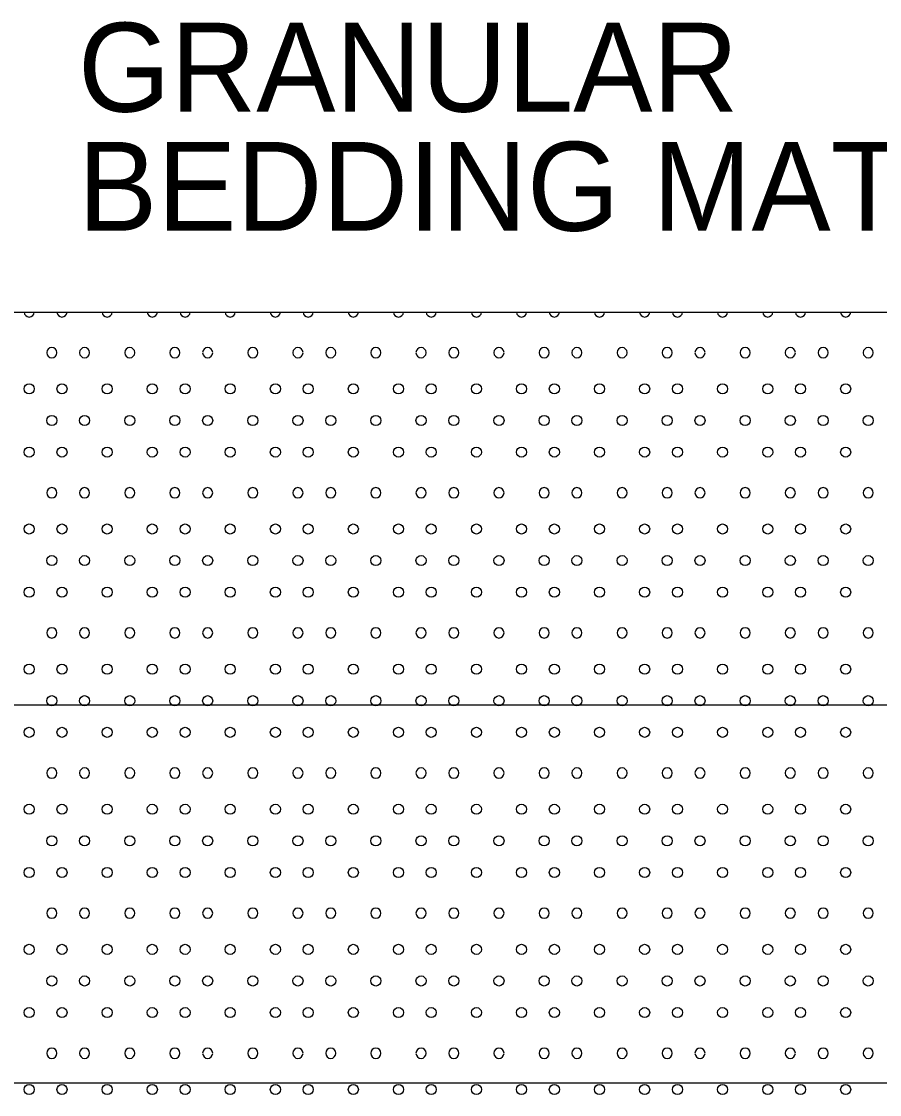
# Model space of a CAD drawing. Extents: x 49991.4 to 50021, y 49987.6 to 50011.4.
# Drawn here: x 50019.363 to 50019.942, y 50006.557 to 50007.281 of the extents above; entities that cross this region are included whole.
import ezdxf

# ---------------------------------------------------------------- set-up
doc = ezdxf.new("R2010")
doc.units = 0
doc.layers.add('Level 1', color=7, linetype='Continuous')
doc.layers.add('Level 2', color=7, linetype='Continuous')

msp = doc.modelspace()

# ---------------------------------------------------------------- linework, layer by layer
at = {"layer": 'Level 1'}
for p, q in [((50017.1193, 50007.085), (50020.46747, 50007.085)), ((50017.0193, 50006.81976), (50020.46747, 50006.81976)), ((50020.46747, 50006.56447), (50017.12756, 50006.5644))]:
    msp.add_line(p, q, dxfattribs=at)
for centre in [(50019.36773, 50007.03318), (50019.38987, 50007.03318), (50019.42035, 50007.03318), (50019.45083, 50007.03318), (50019.47297, 50007.03318), (50019.50345, 50007.03318), (50019.53393, 50007.03318), (50019.55607, 50007.03318), (50019.58655, 50007.03318), (50019.61703, 50007.03318), (50019.63917, 50007.03318), (50019.66965, 50007.03318), (50019.70013, 50007.03318), (50019.72227, 50007.03318), (50019.75275, 50007.03318), (50019.78323, 50007.03318), (50019.80537, 50007.03318), (50019.83585, 50007.03318), (50019.86633, 50007.03318), (50019.88847, 50007.03318), (50019.91895, 50007.03318), (50019.38297, 50007.01185), (50019.40511, 50007.01185), (50019.43559, 50007.01185), (50019.43559, 50007.01185), (50019.46607, 50007.01185), (50019.48821, 50007.01185), (50019.51869, 50007.01185), (50019.51869, 50007.01185), (50019.54917, 50007.01185), (50019.57131, 50007.01185), (50019.60179, 50007.01185), (50019.60179, 50007.01185), (50019.63227, 50007.01185), (50019.65441, 50007.01185), (50019.68489, 50007.01185), (50019.68489, 50007.01185), (50019.71537, 50007.01185), (50019.73751, 50007.01185), (50019.76799, 50007.01185), (50019.76799, 50007.01185), (50019.79847, 50007.01185), (50019.82061, 50007.01185), (50019.85109, 50007.01185), (50019.85109, 50007.01185), (50019.88157, 50007.01185), (50019.90371, 50007.01185), (50019.93419, 50007.01185), (50019.93419, 50007.01185), (50019.36773, 50006.99051), (50019.38987, 50006.99051), (50019.42035, 50006.99051), (50019.45083, 50006.99051), (50019.47297, 50006.99051), (50019.50345, 50006.99051), (50019.53393, 50006.99051), (50019.55607, 50006.99051), (50019.58655, 50006.99051), (50019.61703, 50006.99051), (50019.63917, 50006.99051), (50019.66965, 50006.99051), (50019.70013, 50006.99051), (50019.72227, 50006.99051), (50019.75275, 50006.99051), (50019.78323, 50006.99051), (50019.80537, 50006.99051), (50019.83585, 50006.99051), (50019.86633, 50006.99051), (50019.88847, 50006.99051), (50019.91895, 50006.99051), (50019.36773, 50006.93858), (50019.38987, 50006.93858), (50019.42035, 50006.93858), (50019.45083, 50006.93858), (50019.47297, 50006.93858), (50019.50345, 50006.93858), (50019.53393, 50006.93858), (50019.55607, 50006.93858), (50019.58655, 50006.93858), (50019.61703, 50006.93858), (50019.63917, 50006.93858), (50019.66965, 50006.93858), (50019.70013, 50006.93858), (50019.72227, 50006.93858), (50019.75275, 50006.93858), (50019.78323, 50006.93858), (50019.80537, 50006.93858), (50019.83585, 50006.93858), (50019.86633, 50006.93858), (50019.88847, 50006.93858), (50019.91895, 50006.93858), (50019.38297, 50006.91725), (50019.40511, 50006.91725), (50019.43559, 50006.91725), (50019.43559, 50006.91725), (50019.46607, 50006.91725), (50019.48821, 50006.91725), (50019.51869, 50006.91725), (50019.51869, 50006.91725), (50019.54917, 50006.91725), (50019.57131, 50006.91725), (50019.60179, 50006.91725), (50019.60179, 50006.91725), (50019.63227, 50006.91725), (50019.65441, 50006.91725), (50019.68489, 50006.91725), (50019.68489, 50006.91725), (50019.71537, 50006.91725), (50019.73751, 50006.91725), (50019.76799, 50006.91725), (50019.76799, 50006.91725), (50019.79847, 50006.91725), (50019.82061, 50006.91725), (50019.85109, 50006.91725), (50019.85109, 50006.91725), (50019.88157, 50006.91725), (50019.90371, 50006.91725), (50019.93419, 50006.91725), (50019.93419, 50006.91725), (50019.36773, 50006.89591), (50019.38987, 50006.89591), (50019.42035, 50006.89591), (50019.45083, 50006.89591), (50019.47297, 50006.89591), (50019.50345, 50006.89591), (50019.53393, 50006.89591), (50019.55607, 50006.89591), (50019.58655, 50006.89591), (50019.61703, 50006.89591), (50019.63917, 50006.89591), (50019.66965, 50006.89591), (50019.70013, 50006.89591), (50019.72227, 50006.89591), (50019.75275, 50006.89591), (50019.78323, 50006.89591), (50019.80537, 50006.89591), (50019.83585, 50006.89591), (50019.86633, 50006.89591), (50019.88847, 50006.89591), (50019.91895, 50006.89591), (50019.36773, 50006.84398), (50019.38987, 50006.84398), (50019.42035, 50006.84398), (50019.45083, 50006.84398), (50019.47297, 50006.84398), (50019.50345, 50006.84398), (50019.53393, 50006.84398), (50019.55607, 50006.84398), (50019.58655, 50006.84398), (50019.61703, 50006.84398), (50019.63917, 50006.84398), (50019.66965, 50006.84398), (50019.70013, 50006.84398), (50019.72227, 50006.84398), (50019.75275, 50006.84398), (50019.78323, 50006.84398), (50019.80537, 50006.84398), (50019.83585, 50006.84398), (50019.86633, 50006.84398), (50019.88847, 50006.84398), (50019.91895, 50006.84398), (50019.38297, 50006.82265), (50019.40511, 50006.82265), (50019.43559, 50006.82265), (50019.43559, 50006.82265), (50019.46607, 50006.82265), (50019.48821, 50006.82265), (50019.51869, 50006.82265), (50019.51869, 50006.82265), (50019.54917, 50006.82265), (50019.57131, 50006.82265), (50019.60179, 50006.82265), (50019.60179, 50006.82265), (50019.63227, 50006.82265), (50019.65441, 50006.82265), (50019.68489, 50006.82265), (50019.68489, 50006.82265), (50019.71537, 50006.82265), (50019.73751, 50006.82265), (50019.76799, 50006.82265), (50019.76799, 50006.82265), (50019.79847, 50006.82265), (50019.82061, 50006.82265), (50019.85109, 50006.82265), (50019.85109, 50006.82265), (50019.88157, 50006.82265), (50019.90371, 50006.82265), (50019.93419, 50006.82265), (50019.93419, 50006.82265), (50019.36773, 50006.80131), (50019.38987, 50006.80131), (50019.42035, 50006.80131), (50019.45083, 50006.80131), (50019.47297, 50006.80131), (50019.50345, 50006.80131), (50019.53393, 50006.80131), (50019.55607, 50006.80131), (50019.58655, 50006.80131), (50019.61703, 50006.80131), (50019.63917, 50006.80131), (50019.66965, 50006.80131), (50019.70013, 50006.80131), (50019.72227, 50006.80131), (50019.75275, 50006.80131), (50019.78323, 50006.80131), (50019.80537, 50006.80131), (50019.83585, 50006.80131), (50019.86633, 50006.80131), (50019.88847, 50006.80131), (50019.91895, 50006.80131), (50019.36773, 50006.74938), (50019.38987, 50006.74938), (50019.42035, 50006.74938), (50019.45083, 50006.74938), (50019.47297, 50006.74938), (50019.50345, 50006.74938), (50019.53393, 50006.74938), (50019.55607, 50006.74938), (50019.58655, 50006.74938), (50019.61703, 50006.74938), (50019.63917, 50006.74938), (50019.66965, 50006.74938), (50019.70013, 50006.74938), (50019.72227, 50006.74938), (50019.75275, 50006.74938), (50019.78323, 50006.74938), (50019.80537, 50006.74938), (50019.83585, 50006.74938), (50019.86633, 50006.74938), (50019.88847, 50006.74938), (50019.91895, 50006.74938), (50019.38297, 50006.72805), (50019.40511, 50006.72805), (50019.43559, 50006.72805), (50019.43559, 50006.72805), (50019.46607, 50006.72805), (50019.48821, 50006.72805), (50019.51869, 50006.72805), (50019.51869, 50006.72805), (50019.54917, 50006.72805), (50019.57131, 50006.72805), (50019.60179, 50006.72805), (50019.60179, 50006.72805), (50019.63227, 50006.72805), (50019.65441, 50006.72805), (50019.68489, 50006.72805), (50019.68489, 50006.72805), (50019.71537, 50006.72805), (50019.73751, 50006.72805), (50019.76799, 50006.72805), (50019.76799, 50006.72805), (50019.79847, 50006.72805), (50019.82061, 50006.72805), (50019.85109, 50006.72805), (50019.85109, 50006.72805), (50019.88157, 50006.72805), (50019.90371, 50006.72805), (50019.93419, 50006.72805), (50019.93419, 50006.72805), (50019.36773, 50006.70671), (50019.38987, 50006.70671), (50019.42035, 50006.70671), (50019.45083, 50006.70671), (50019.47297, 50006.70671), (50019.50345, 50006.70671), (50019.53393, 50006.70671), (50019.55607, 50006.70671), (50019.58655, 50006.70671), (50019.61703, 50006.70671), (50019.63917, 50006.70671), (50019.66965, 50006.70671), (50019.70013, 50006.70671), (50019.72227, 50006.70671), (50019.75275, 50006.70671), (50019.78323, 50006.70671), (50019.80537, 50006.70671), (50019.83585, 50006.70671), (50019.86633, 50006.70671), (50019.88847, 50006.70671), (50019.91895, 50006.70671), (50019.36773, 50006.65478), (50019.38987, 50006.65478), (50019.42035, 50006.65478), (50019.45083, 50006.65478), (50019.47297, 50006.65478), (50019.50345, 50006.65478), (50019.53393, 50006.65478), (50019.55607, 50006.65478), (50019.58655, 50006.65478), (50019.61703, 50006.65478), (50019.63917, 50006.65478), (50019.66965, 50006.65478), (50019.70013, 50006.65478), (50019.72227, 50006.65478), (50019.75275, 50006.65478), (50019.78323, 50006.65478), (50019.80537, 50006.65478), (50019.83585, 50006.65478), (50019.86633, 50006.65478), (50019.88847, 50006.65478), (50019.91895, 50006.65478), (50019.38297, 50006.63345), (50019.40511, 50006.63345), (50019.43559, 50006.63345), (50019.43559, 50006.63345), (50019.46607, 50006.63345), (50019.48821, 50006.63345), (50019.51869, 50006.63345), (50019.51869, 50006.63345), (50019.54917, 50006.63345), (50019.57131, 50006.63345), (50019.60179, 50006.63345), (50019.60179, 50006.63345), (50019.63227, 50006.63345), (50019.65441, 50006.63345), (50019.68489, 50006.63345), (50019.68489, 50006.63345), (50019.71537, 50006.63345), (50019.73751, 50006.63345), (50019.76799, 50006.63345), (50019.76799, 50006.63345), (50019.79847, 50006.63345), (50019.82061, 50006.63345), (50019.85109, 50006.63345), (50019.85109, 50006.63345), (50019.88157, 50006.63345), (50019.90371, 50006.63345), (50019.93419, 50006.63345), (50019.93419, 50006.63345), (50019.36773, 50006.61211), (50019.38987, 50006.61211), (50019.42035, 50006.61211), (50019.45083, 50006.61211), (50019.47297, 50006.61211), (50019.50345, 50006.61211), (50019.53393, 50006.61211), (50019.55607, 50006.61211), (50019.58655, 50006.61211), (50019.61703, 50006.61211), (50019.63917, 50006.61211), (50019.66965, 50006.61211), (50019.70013, 50006.61211), (50019.72227, 50006.61211), (50019.75275, 50006.61211), (50019.78323, 50006.61211), (50019.80537, 50006.61211), (50019.83585, 50006.61211), (50019.86633, 50006.61211), (50019.88847, 50006.61211), (50019.91895, 50006.61211), (50019.36773, 50006.56018), (50019.38987, 50006.56018), (50019.42035, 50006.56018), (50019.45083, 50006.56018), (50019.47297, 50006.56018), (50019.50345, 50006.56018), (50019.53393, 50006.56018), (50019.55607, 50006.56018), (50019.58655, 50006.56018), (50019.61703, 50006.56018), (50019.63917, 50006.56018), (50019.66965, 50006.56018), (50019.70013, 50006.56018), (50019.72227, 50006.56018), (50019.75275, 50006.56018), (50019.78323, 50006.56018), (50019.80537, 50006.56018), (50019.83585, 50006.56018), (50019.86633, 50006.56018), (50019.88847, 50006.56018), (50019.91895, 50006.56018)]:
    msp.add_circle(centre, 0.00341, dxfattribs=at)
for centre, start, end in [((50019.36773, 50007.08511), 181.83358, 358.16642), ((50019.38987, 50007.08511), 181.83358, 358.16642), ((50019.42035, 50007.08511), 181.83358, 358.16642), ((50019.45083, 50007.08511), 181.83358, 358.16642), ((50019.47297, 50007.08511), 181.83358, 358.16642), ((50019.50345, 50007.08511), 181.83358, 358.16642), ((50019.53393, 50007.08511), 181.83358, 358.16642), ((50019.55607, 50007.08511), 181.83358, 358.16642), ((50019.58655, 50007.08511), 181.83358, 358.16642), ((50019.61703, 50007.08511), 181.83358, 358.16642), ((50019.63917, 50007.08511), 181.83358, 358.16642), ((50019.66965, 50007.08511), 181.83358, 358.16642), ((50019.70013, 50007.08511), 181.83358, 358.16642), ((50019.72227, 50007.08511), 181.83358, 358.16642), ((50019.75275, 50007.08511), 181.83358, 358.16642), ((50019.78323, 50007.08511), 181.83358, 358.16642), ((50019.80537, 50007.08511), 181.83358, 358.16642), ((50019.83585, 50007.08511), 181.83358, 358.16642), ((50019.86633, 50007.08511), 181.83358, 358.16642), ((50019.88847, 50007.08511), 181.83358, 358.16642), ((50019.91895, 50007.08511), 181.83358, 358.16642), ((50019.38297, 50007.05768), 0, 180), ((50019.38297, 50007.05757), 180, 0), ((50019.40511, 50007.05768), 0, 180), ((50019.40511, 50007.05757), 180, 0), ((50019.43559, 50007.05768), 0, 180), ((50019.43559, 50007.05757), 180, 0), ((50019.43559, 50007.05757), 180, 0), ((50019.46607, 50007.05768), 0, 180), ((50019.46607, 50007.05757), 180, 0), ((50019.48821, 50007.05768), 0, 180), ((50019.48821, 50007.05757), 180, 0), ((50019.51869, 50007.05768), 0, 180), ((50019.51869, 50007.05757), 180, 0), ((50019.51869, 50007.05757), 180, 0), ((50019.54917, 50007.05768), 0, 180), ((50019.54917, 50007.05757), 180, 0), ((50019.57131, 50007.05768), 0, 180), ((50019.57131, 50007.05757), 180, 0), ((50019.60179, 50007.05768), 0, 180), ((50019.60179, 50007.05757), 180, 0), ((50019.60179, 50007.05757), 180, 0), ((50019.63227, 50007.05768), 0, 180), ((50019.63227, 50007.05757), 180, 0), ((50019.65441, 50007.05768), 0, 180), ((50019.65441, 50007.05757), 180, 0), ((50019.68489, 50007.05768), 0, 180), ((50019.68489, 50007.05757), 180, 0), ((50019.68489, 50007.05757), 180, 0), ((50019.71537, 50007.05768), 0, 180), ((50019.71537, 50007.05757), 180, 0), ((50019.73751, 50007.05768), 0, 180), ((50019.73751, 50007.05757), 180, 0), ((50019.76799, 50007.05768), 0, 180), ((50019.76799, 50007.05757), 180, 0), ((50019.76799, 50007.05757), 180, 0), ((50019.79847, 50007.05768), 0, 180), ((50019.79847, 50007.05757), 180, 0), ((50019.82061, 50007.05768), 0, 180), ((50019.82061, 50007.05757), 180, 0), ((50019.85109, 50007.05768), 0, 180), ((50019.85109, 50007.05757), 180, 0), ((50019.85109, 50007.05757), 180, 0), ((50019.88157, 50007.05768), 0, 180), ((50019.88157, 50007.05757), 180, 0), ((50019.90371, 50007.05768), 0, 180), ((50019.90371, 50007.05757), 180, 0), ((50019.93419, 50007.05768), 0, 180), ((50019.93419, 50007.05757), 180, 0), ((50019.93419, 50007.05757), 180, 0), ((50019.38297, 50006.96308), 0, 180), ((50019.38297, 50006.96297), 180, 0), ((50019.40511, 50006.96308), 0, 180), ((50019.40511, 50006.96297), 180, 0), ((50019.43559, 50006.96308), 0, 180), ((50019.43559, 50006.96297), 180, 0), ((50019.43559, 50006.96297), 180, 0), ((50019.46607, 50006.96308), 0, 180), ((50019.46607, 50006.96297), 180, 0), ((50019.48821, 50006.96308), 0, 180), ((50019.48821, 50006.96297), 180, 0), ((50019.51869, 50006.96308), 0, 180), ((50019.51869, 50006.96297), 180, 0), ((50019.51869, 50006.96297), 180, 0), ((50019.54917, 50006.96308), 0, 180), ((50019.54917, 50006.96297), 180, 0), ((50019.57131, 50006.96308), 0, 180), ((50019.57131, 50006.96297), 180, 0), ((50019.60179, 50006.96308), 0, 180), ((50019.60179, 50006.96297), 180, 0), ((50019.60179, 50006.96297), 180, 0), ((50019.63227, 50006.96308), 0, 180), ((50019.63227, 50006.96297), 180, 0), ((50019.65441, 50006.96308), 0, 180), ((50019.65441, 50006.96297), 180, 0), ((50019.68489, 50006.96308), 0, 180), ((50019.68489, 50006.96297), 180, 0), ((50019.71537, 50006.96308), 0, 180), ((50019.71537, 50006.96297), 180, 0), ((50019.73751, 50006.96308), 0, 180), ((50019.73751, 50006.96297), 180, 0), ((50019.76799, 50006.96308), 0, 180), ((50019.76799, 50006.96297), 180, 0), ((50019.76799, 50006.96297), 180, 0), ((50019.79847, 50006.96308), 0, 180), ((50019.79847, 50006.96297), 180, 0), ((50019.82061, 50006.96308), 0, 180), ((50019.82061, 50006.96297), 180, 0), ((50019.85109, 50006.96308), 0, 180), ((50019.85109, 50006.96297), 180, 0), ((50019.85109, 50006.96297), 180, 0), ((50019.88157, 50006.96308), 0, 180), ((50019.88157, 50006.96297), 180, 0), ((50019.90371, 50006.96308), 0, 180), ((50019.90371, 50006.96297), 180, 0), ((50019.93419, 50006.96308), 0, 180), ((50019.93419, 50006.96297), 180, 0), ((50019.93419, 50006.96297), 180, 0), ((50019.38297, 50006.86848), 0, 180), ((50019.38297, 50006.86837), 180, 0), ((50019.40511, 50006.86848), 0, 180), ((50019.40511, 50006.86837), 180, 0), ((50019.43559, 50006.86848), 0, 180), ((50019.43559, 50006.86837), 180, 0), ((50019.43559, 50006.86837), 180, 0), ((50019.46607, 50006.86848), 0, 180), ((50019.46607, 50006.86837), 180, 0), ((50019.48821, 50006.86848), 0, 180), ((50019.48821, 50006.86837), 180, 0), ((50019.51869, 50006.86848), 0, 180), ((50019.51869, 50006.86837), 180, 0), ((50019.51869, 50006.86837), 180, 0), ((50019.54917, 50006.86848), 0, 180), ((50019.54917, 50006.86837), 180, 0), ((50019.57131, 50006.86848), 0, 180), ((50019.57131, 50006.86837), 180, 0), ((50019.60179, 50006.86848), 0, 180), ((50019.60179, 50006.86837), 180, 0), ((50019.60179, 50006.86837), 180, 0), ((50019.63227, 50006.86848), 0, 180), ((50019.63227, 50006.86837), 180, 0), ((50019.65441, 50006.86848), 0, 180), ((50019.65441, 50006.86837), 180, 0), ((50019.68489, 50006.86848), 0, 180), ((50019.68489, 50006.86837), 180, 0), ((50019.68489, 50006.86837), 180, 0), ((50019.71537, 50006.86848), 0, 180), ((50019.71537, 50006.86837), 180, 0), ((50019.73751, 50006.86848), 0, 180), ((50019.73751, 50006.86837), 180, 0), ((50019.76799, 50006.86848), 0, 180), ((50019.76799, 50006.86837), 180, 0), ((50019.76799, 50006.86837), 180, 0), ((50019.79847, 50006.86848), 0, 180), ((50019.79847, 50006.86837), 180, 0), ((50019.82061, 50006.86848), 0, 180), ((50019.82061, 50006.86837), 180, 0), ((50019.85109, 50006.86848), 0, 180), ((50019.85109, 50006.86837), 180, 0), ((50019.85109, 50006.86837), 180, 0), ((50019.88157, 50006.86848), 0, 180), ((50019.88157, 50006.86837), 180, 0), ((50019.90371, 50006.86848), 0, 180), ((50019.90371, 50006.86837), 180, 0), ((50019.93419, 50006.86848), 0, 180), ((50019.93419, 50006.86837), 180, 0), ((50019.93419, 50006.86837), 180, 0), ((50019.38297, 50006.77388), 0, 180), ((50019.38297, 50006.77377), 180, 0), ((50019.40511, 50006.77388), 0, 180), ((50019.40511, 50006.77377), 180, 0), ((50019.43559, 50006.77388), 0, 180), ((50019.43559, 50006.77377), 180, 0), ((50019.43559, 50006.77377), 180, 0), ((50019.46607, 50006.77388), 0, 180), ((50019.46607, 50006.77377), 180, 0), ((50019.48821, 50006.77388), 0, 180), ((50019.48821, 50006.77377), 180, 0), ((50019.51869, 50006.77388), 0, 180), ((50019.51869, 50006.77377), 180, 0), ((50019.51869, 50006.77377), 180, 0), ((50019.54917, 50006.77388), 0, 180), ((50019.54917, 50006.77377), 180, 0), ((50019.57131, 50006.77388), 0, 180), ((50019.57131, 50006.77377), 180, 0), ((50019.60179, 50006.77388), 0, 180), ((50019.60179, 50006.77377), 180, 0), ((50019.60179, 50006.77377), 180, 0), ((50019.63227, 50006.77388), 0, 180), ((50019.63227, 50006.77377), 180, 0), ((50019.65441, 50006.77388), 0, 180), ((50019.65441, 50006.77377), 180, 0), ((50019.68489, 50006.77388), 0, 180), ((50019.68489, 50006.77377), 180, 0), ((50019.68489, 50006.77377), 180, 0), ((50019.71537, 50006.77388), 0, 180), ((50019.71537, 50006.77377), 180, 0), ((50019.73751, 50006.77388), 0, 180), ((50019.73751, 50006.77377), 180, 0), ((50019.76799, 50006.77388), 0, 180), ((50019.76799, 50006.77377), 180, 0), ((50019.76799, 50006.77377), 180, 0), ((50019.79847, 50006.77388), 0, 180), ((50019.79847, 50006.77377), 180, 0), ((50019.82061, 50006.77388), 0, 180), ((50019.82061, 50006.77377), 180, 0), ((50019.85109, 50006.77388), 0, 180), ((50019.85109, 50006.77377), 180, 0), ((50019.85109, 50006.77377), 180, 0), ((50019.88157, 50006.77388), 0, 180), ((50019.88157, 50006.77377), 180, 0), ((50019.90371, 50006.77388), 0, 180), ((50019.90371, 50006.77377), 180, 0), ((50019.93419, 50006.77388), 0, 180), ((50019.93419, 50006.77377), 180, 0), ((50019.93419, 50006.77377), 180, 0), ((50019.38297, 50006.67928), 0, 180), ((50019.38297, 50006.67917), 180, 0), ((50019.40511, 50006.67928), 0, 180), ((50019.40511, 50006.67917), 180, 0), ((50019.43559, 50006.67928), 0, 180), ((50019.43559, 50006.67917), 180, 0), ((50019.43559, 50006.67917), 180, 0), ((50019.46607, 50006.67928), 0, 180), ((50019.46607, 50006.67917), 180, 0), ((50019.48821, 50006.67928), 0, 180), ((50019.48821, 50006.67917), 180, 0), ((50019.51869, 50006.67928), 0, 180), ((50019.51869, 50006.67917), 180, 0), ((50019.51869, 50006.67917), 180, 0), ((50019.54917, 50006.67928), 0, 180), ((50019.54917, 50006.67917), 180, 0), ((50019.57131, 50006.67928), 0, 180), ((50019.57131, 50006.67917), 180, 0), ((50019.60179, 50006.67928), 0, 180), ((50019.60179, 50006.67917), 180, 0), ((50019.60179, 50006.67917), 180, 0), ((50019.63227, 50006.67928), 0, 180), ((50019.63227, 50006.67917), 180, 0), ((50019.65441, 50006.67928), 0, 180), ((50019.65441, 50006.67917), 180, 0), ((50019.68489, 50006.67928), 0, 180), ((50019.68489, 50006.67917), 180, 0), ((50019.68489, 50006.67917), 180, 0), ((50019.71537, 50006.67928), 0, 180), ((50019.71537, 50006.67917), 180, 0), ((50019.73751, 50006.67928), 0, 180), ((50019.73751, 50006.67917), 180, 0), ((50019.76799, 50006.67928), 0, 180), ((50019.76799, 50006.67917), 180, 0), ((50019.76799, 50006.67917), 180, 0), ((50019.79847, 50006.67928), 0, 180), ((50019.79847, 50006.67917), 180, 0), ((50019.82061, 50006.67928), 0, 180), ((50019.82061, 50006.67917), 180, 0), ((50019.85109, 50006.67928), 0, 180), ((50019.85109, 50006.67917), 180, 0), ((50019.85109, 50006.67917), 180, 0), ((50019.88157, 50006.67928), 0, 180), ((50019.88157, 50006.67917), 180, 0), ((50019.90371, 50006.67928), 0, 180), ((50019.90371, 50006.67917), 180, 0), ((50019.93419, 50006.67928), 0, 180), ((50019.93419, 50006.67917), 180, 0), ((50019.93419, 50006.67917), 180, 0), ((50019.38297, 50006.58468), 0, 180), ((50019.38297, 50006.58457), 180, 0), ((50019.40511, 50006.58468), 0, 180), ((50019.40511, 50006.58457), 180, 0), ((50019.43559, 50006.58468), 0, 180), ((50019.43559, 50006.58457), 180, 0), ((50019.43559, 50006.58457), 180, 0), ((50019.46607, 50006.58468), 0, 180), ((50019.46607, 50006.58457), 180, 0), ((50019.48821, 50006.58468), 0, 180), ((50019.48821, 50006.58457), 180, 0), ((50019.51869, 50006.58468), 0, 180), ((50019.51869, 50006.58457), 180, 0), ((50019.51869, 50006.58457), 180, 0), ((50019.54917, 50006.58468), 0, 180), ((50019.54917, 50006.58457), 180, 0), ((50019.57131, 50006.58468), 0, 180), ((50019.57131, 50006.58457), 180, 0), ((50019.60179, 50006.58468), 0, 180), ((50019.60179, 50006.58457), 180, 0), ((50019.60179, 50006.58457), 180, 0), ((50019.63227, 50006.58468), 0, 180), ((50019.63227, 50006.58457), 180, 0), ((50019.65441, 50006.58468), 0, 180), ((50019.65441, 50006.58457), 180, 0), ((50019.68489, 50006.58468), 0, 180), ((50019.68489, 50006.58457), 180, 0), ((50019.68489, 50006.58457), 180, 0), ((50019.71537, 50006.58468), 0, 180), ((50019.71537, 50006.58457), 180, 0), ((50019.73751, 50006.58468), 0, 180), ((50019.73751, 50006.58457), 180, 0), ((50019.76799, 50006.58468), 0, 180), ((50019.76799, 50006.58457), 180, 0), ((50019.76799, 50006.58457), 180, 0), ((50019.79847, 50006.58468), 0, 180), ((50019.79847, 50006.58457), 180, 0), ((50019.82061, 50006.58468), 0, 180), ((50019.82061, 50006.58457), 180, 0), ((50019.85109, 50006.58468), 0, 180), ((50019.85109, 50006.58457), 180, 0), ((50019.85109, 50006.58457), 180, 0), ((50019.88157, 50006.58468), 0, 180), ((50019.88157, 50006.58457), 180, 0), ((50019.90371, 50006.58468), 0, 180), ((50019.90371, 50006.58457), 180, 0), ((50019.93419, 50006.58468), 0, 180), ((50019.93419, 50006.58457), 180, 0), ((50019.93419, 50006.58457), 180, 0)]:
    msp.add_arc(centre, 0.00341, start, end, dxfattribs=at)

# ---------------------------------------------------------------- texts
at = {"layer": 'Level 2'}
for s, p in [('GRANULAR', (50019.40068, 50007.22033)), ('BEDDING MATERIAL', (50019.40068, 50007.13993))]:
    msp.add_text(s, height=0.06, dxfattribs=at).set_placement(p)

doc.saveas('drawing.dxf')
